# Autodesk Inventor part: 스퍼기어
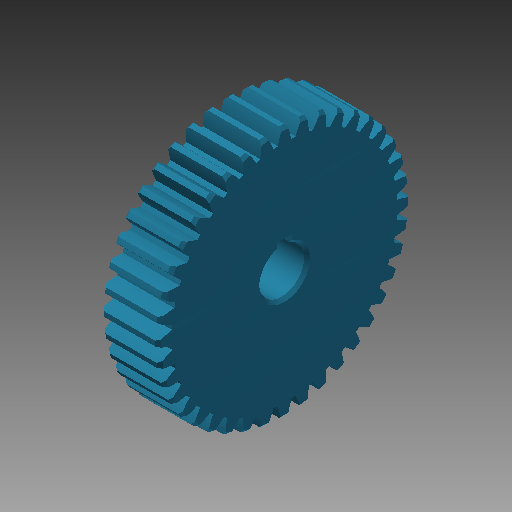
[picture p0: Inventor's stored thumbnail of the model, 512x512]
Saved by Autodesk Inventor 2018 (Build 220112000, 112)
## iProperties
Created: 2018-11
Part Number: 스퍼기어
Material: 알루미늄 6061
Document SubType Name: Modeling
Designer: mduedu
Categories: <?xml version="1.0" encoding="UTF-16"?> <MemberInstance><Categories><FamilyTemplate><FamilyTemplateParameter ValueType="xs:double" Id="1" ObjectReferenceKey="da
Density: 1 g/cm^3
Appearance: 터키옥색
CustomPartVersion: 1
Author: mduedu
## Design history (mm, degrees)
sketch "Sketch1"
  geometry: C1 r 42 at (0, 0)
  constraints: 1 centre point
  dimensions: "d0" = 83.99905 diameter of C1 (= da_da)
extrude "Extrusion1" new body sketch "Sketch1" distance "d1" = 19 (= da_b); taper "d2" = 0 deg
workplane "Work Plane2"
sketch "Sketch2"
  geometry: C1 r 42 at (0, 0) reference; C2 r 40.05 at (0, 0)
  constraints: 1 centre point, 1 coincident
  dimensions: "d3" = 80.10038 diameter of C2 (= da_dw)
feature "피치 지름" sketch "Sketch2" dims "d4" = 10, "d5" = 0
workplane "Work Plane8"
workplane "Work Plane9"
feature "스퍼 기어" dims "da_b" = 19, "da_d" = 80, "da_aw" = 80.10038, "da_da" = 83.99905, "da_df" = 75, "da_dw" = 80.10038, angle "da_beta" = 0 deg, "da_lefttooth" = 0, "da_righttooth" = 0
sketch "스케치3"
  geometry: L1 (-42, 19)-(42, 19) reference; L2 (42, 19)-(42, 0) reference; L3 (42, 0)-(-42, 0) reference; L4 (-42, 0)-(-42, 19) reference; L5 (0, 0)-(0, 19); L6 (42, 0)-(41, 0); L7 (42, 1)-(42, 0); L8 (42, 19)-(41, 19); L9 (42, 18)-(42, 19); L10 (41, 19)-(42, 18); L11 (41, 0)-(42, 1)
  constraints: 14 end point, 2 horizontal, 2 vertical, 1 midpoint
  dimensions: "d49" = 1 distance from line of L8.end L2; "d50" = 1 horizontal distance of L8.end L9.start; "d51" = 1 horizontal distance of L6.end L7.start; "d52" = 1 horizontal distance of L6.end L7.start
revolve "회전1" sketch "스케치3" stored, may be unused: angle "d53" = 90 deg
sketch "스케치4"
  geometry: L1 (-2.5, 7.071)-(2.5, 7.071); L2 (2.5, 7.071)-(2.5, 9.8); L3 (2.5, 9.8)-(-2.5, 9.8); L4 (-2.5, 9.8)-(-2.5, 7.071); A1 r 7.5 centre (0, 0) between (-2.5, 7.071) and (2.5, 7.071); 1 further point
  constraints: 8 end point, 2 parallel, 2 point on circle, 1 centre point, 1 coincident, 1 horizontal, 1 perpendicular
  dimensions: "d54" = 15 diameter of A1; "d56" = 17.3 dimension on A1 L3; "d57" = 5 distance of L2.end L3.end
extrude "돌출2" cut sketch "스케치4" extent not by distance; stored distance "d58" = 10; taper "d59" = 0 deg
chamfer "모따기1" distance "d60" = 1; stored, may be unused: second distance "d61" = 2, angle "d62" = 45 deg
sketch "스케치5"
  geometry: C1 r 17.5 at (0, 0); C2 r 28.5 at (0, 0); 1 further point
  constraints: 2 centre point, 2 coincident
  dimensions: "d63" = 35 diameter of C1; "d64" = 57 diameter of C2
extrude "돌출3" cut sketch "스케치5" distance "d65" = 9.5; taper "d66" = 0 deg
fillet "모깎기1" dims "d67" = 3
chamfer "모따기2" distance "d68" = 0.5; stored, may be unused: second distance "d69" = 2, angle "d70" = 45 deg
body "Solid1"
body "Srf1"
node "절단 모서리 투영1"
other parameters: "d16" = 80.10038 (= da_aw), "d17" = 0, "d34" = 4.5 deg (computed from da_z), "d39" = 0, "d41" = 0, "d43" = 80.10038 (= da_aw), "d46" = 80.10038 (= da_aw), "d47" = 0, "d48" = 0
